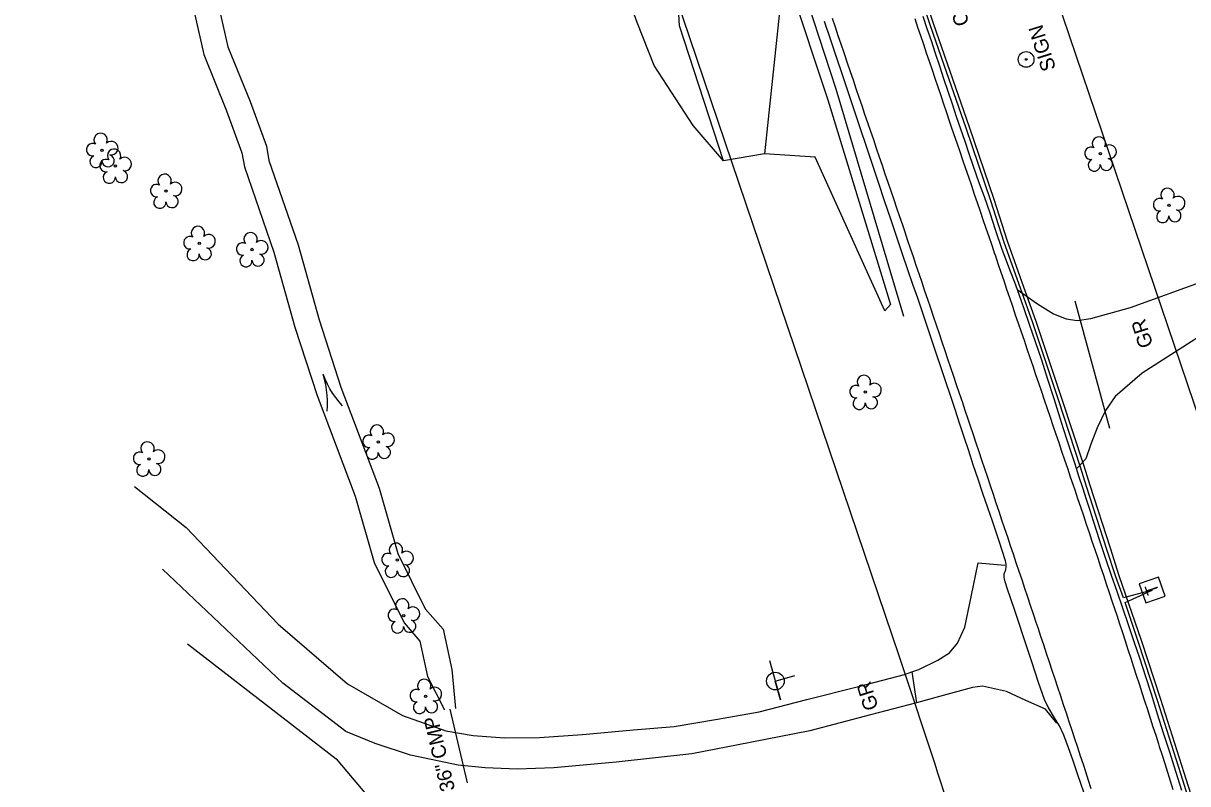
# Model space of a CAD drawing. Extents: x 472260 to 482161, y 489063 to 507124.
# Drawn here: x 481024.5 to 481347.6, y 491870.7 to 492081.8 of the extents above; entities that cross this region are included whole.
import ezdxf

# ---------------------------------------------------------------- set-up
doc = ezdxf.new("R2010")
doc.units = 0
for name, color, linetype in [('Exist Structure Minor Drop Inlet Cogo Elevation', 7, 'Continuous'), ('Exist Structure Minor Pipes CMP 30 Inch', 7, 'Continuous'), ('Prop Drainage Structure Catch Basin Convert From Junction Box Label', 7, 'Continuous'), ('Prop Drainage Structure Drop Inlet Grate 2 Narrow Slots and Sag Grates 840 24 CELL', 7, 'Continuous'), ('Prop Drainage Structure Drop Inlet Grate 2 Wide Slots and Flat Grates 840 20 Label', 7, 'Continuous'), ('Prop Drainage Structure Pipe CSP 30in Label', 7, 'Continuous'), ('Prop Drainage Structure Pipe RCP 15in Class III', 7, 'Continuous'), ('Prop Drainage Structure Pipe RCP 18in Class III', 7, 'Continuous'), ('Prop Drainage Structure Pipe RCP 24in Class III', 7, 'Continuous'), ('Prop Drainage Structure Pipe RCP 48in Class IV', 7, 'Continuous'), ('Prop Drainage Structure Pipe Stub Out CELL', 7, 'Continuous'), ('Prop Drainage Structure Plot Symbol 50 Scale CELL', 7, 'Continuous'), ('Prop Drainage Structure Tops and Inverts LABEL', 7, 'Continuous'), ('Prop Earthen Structure Base Ditch Lateral Detail Label', 7, 'Continuous'), ('Prop Earthen Structure Berm Ditch Detail Label', 7, 'Continuous'), ('Prop Earthen Structure Ditch Flow Line', 7, 'Continuous'), ('Prop Earthen Structure False Sump Label', 7, 'Continuous'), ('Prop Erosion Rip Rap Class B', 7, 'Continuous'), ('Prop Erosion Rip Rap Pad at Outlet Label', 7, 'Continuous'), ('Prop Erosion Rip Rap Single Stone CELL', 7, 'Continuous'), ('Scratch_Level_8', 7, 'Continuous')]:
    doc.layers.add(name, color=color, linetype=linetype)

msp = doc.modelspace()

# ---------------------------------------------------------------- linework, layer by layer
at = {"layer": 'Exist Structure Minor Drop Inlet Cogo Elevation'}
for p, q in [((481362.22, 491938.28), (481119.25, 492655.94)), ((481267.5, 491906.22), (481024.53, 492623.87))]:
    msp.add_line(p, q, dxfattribs=at)
msp.add_arc((478607.84, 491005.76), 2807.95, 16.9803, 18.70399, dxfattribs=at)
at = {"layer": 'Prop Drainage Structure Catch Basin Convert From Junction Box Label'}
for p, q in [((481337.73, 491924.43), (481329.76, 491922.32)), ((481330.28, 491921.01), (481337.73, 491924.43))]:
    msp.add_line(p, q, dxfattribs=at)
for points in [[(481326.13, 491936.08), (481320.49, 491953.49), (481318.83, 491958.9), (481312.67, 491977.61), (481305.58, 491998.99), (481302.12, 492008.58), (481297.61, 492021.26), (481293.89, 492032.85), (481287.08, 492052.94), (481280.98, 492070.5), (481277.07, 492081.69), (481270.89, 492100.12), (481264.89, 492117.85), (481258.42, 492137.44), (481251.79, 492155.9), (481249, 492164.34), (481245.98, 492173.6), (481240.1, 492190.35), (481234.35, 492207.23), (481229.22, 492222.9)], [(481325.18, 491935.77), (481319.53, 491953.19), (481317.88, 491958.6), (481311.72, 491977.3), (481304.64, 491998.67), (481301.18, 492008.24), (481296.66, 492020.94), (481292.94, 492032.53), (481286.13, 492052.62), (481280.03, 492070.17), (481276.12, 492081.37), (481269.94, 492099.8), (481263.94, 492117.54), (481257.47, 492137.11), (481250.85, 492155.58), (481248.05, 492164.03), (481245.04, 492173.28), (481239.15, 492190.03), (481233.4, 492206.91), (481228.95, 492220.49)], [(481329.76, 491922.32), (481327.65, 491928.14), (481325.18, 491935.77)], [(481359.82, 491830.99), (481352.88, 491853.99), (481346.61, 491873.75), (481340.18, 491894.14), (481334.78, 491910.5), (481328.6, 491928.45), (481326.13, 491936.08)], [(481358.87, 491830.7), (481351.92, 491853.69), (481345.65, 491873.45), (481339.23, 491893.84), (481333.84, 491910.18), (481330.28, 491921.01)]]:
    msp.add_lwpolyline(points, dxfattribs=at)
at = {"layer": 'Prop Drainage Structure Drop Inlet Grate 2 Narrow Slots and Sag Grates 840 24 CELL'}
for points in [[(481320.81, 491869.27), (481320.06, 491871.65), (481319.3, 491874.03), (481318.67, 491876.04), (481317.88, 491878.41), (481317.1, 491880.78), (481316.31, 491883.15), (481315.52, 491885.53), (481314.73, 491887.9), (481313.95, 491890.27), (481313.16, 491892.64), (481312.37, 491895.02), (481311.58, 491897.39), (481310.8, 491899.76), (481310.01, 491902.13), (481309.22, 491904.5), (481308.43, 491906.88), (481307.65, 491909.25), (481306.86, 491911.62), (481306.07, 491913.99), (481305.59, 491915.44), (481304.8, 491917.81), (481304.01, 491920.18), (481303.21, 491922.55), (481302.42, 491924.92), (481301.63, 491927.29), (481300.83, 491929.66), (481300.04, 491932.03), (481299.25, 491934.4), (481298.45, 491936.77), (481297.66, 491939.14), (481296.87, 491941.51), (481296.07, 491943.88), (481295.28, 491946.25), (481294.49, 491948.62), (481293.7, 491951), (481292.9, 491953.37), (481292.11, 491955.74), (481291.32, 491958.11), (481290.52, 491960.48), (481289.73, 491962.85), (481288.94, 491965.22), (481288.14, 491967.59), (481287.35, 491969.96), (481286.69, 491971.94), (481285.89, 491974.31), (481285.09, 491976.68), (481284.29, 491979.05), (481283.49, 491981.42), (481282.69, 491983.78), (481281.89, 491986.15), (481281.09, 491988.52), (481280.29, 491990.89), (481279.49, 491993.26), (481278.69, 491995.63), (481277.89, 491997.99), (481277.09, 492000.36), (481276.29, 492002.73), (481275.49, 492005.1), (481274.69, 492007.47), (481273.89, 492009.84), (481273.09, 492012.2), (481272.29, 492014.57), (481271.49, 492016.94), (481270.69, 492019.31), (481269.89, 492021.68), (481269.09, 492024.05), (481268.53, 492025.72), (481267.72, 492028.09), (481266.92, 492030.45), (481266.11, 492032.82), (481265.31, 492035.19), (481264.5, 492037.55), (481263.7, 492039.92), (481262.89, 492042.29), (481262.09, 492044.65), (481261.28, 492047.02), (481260.48, 492049.39), (481259.67, 492051.75), (481258.87, 492054.12), (481258.06, 492056.49), (481257.26, 492058.85), (481256.45, 492061.22), (481255.65, 492063.59), (481254.84, 492065.95), (481254.04, 492068.32), (481253.23, 492070.69), (481252.43, 492073.05), (481252.24, 492073.59), (481251.45, 492075.95), (481250.65, 492078.32), (481249.85, 492080.69), (481249.05, 492083.06)], [(481271.85, 492083.08), (481272.65, 492080.71), (481273.46, 492078.34), (481274.26, 492075.97), (481275.06, 492073.6), (481275.86, 492071.24), (481276.66, 492068.87), (481277.46, 492066.5), (481278.26, 492064.13), (481279.06, 492061.76), (481279.86, 492059.4), (481280.66, 492057.03), (481281.46, 492054.66), (481281.92, 492053.31), (481282.73, 492050.95), (481283.53, 492048.58), (481284.34, 492046.22), (481285.15, 492043.85), (481285.95, 492041.49), (481286.76, 492039.12), (481287.57, 492036.75), (481288.37, 492034.39), (481289.18, 492032.02), (481289.99, 492029.66), (481290.8, 492027.29), (481291.6, 492024.92), (481292.41, 492022.56), (481293.22, 492020.19), (481294.02, 492017.83), (481294.15, 492017.47), (481294.95, 492015.1), (481295.75, 492012.73), (481296.56, 492010.37), (481297.36, 492008), (481298.16, 492005.63), (481298.97, 492003.26), (481299.77, 492000.9), (481300.57, 491998.53), (481301.38, 491996.16), (481302.18, 491993.8), (481302.98, 491991.43), (481303.78, 491989.06), (481304.59, 491986.7), (481305.39, 491984.33), (481306.19, 491981.96), (481307, 491979.59), (481307.8, 491977.23), (481308.6, 491974.86), (481309.41, 491972.49), (481310.21, 491970.13), (481311.01, 491967.76), (481311.82, 491965.39), (481312.62, 491963.03), (481313.42, 491960.66), (481314.23, 491958.29), (481315.03, 491955.93), (481315.83, 491953.56), (481316.27, 491952.28), (481317.06, 491949.91), (481317.86, 491947.54), (481318.65, 491945.17), (481319.44, 491942.8), (481320.24, 491940.43), (481321.03, 491938.06), (481321.83, 491935.69), (481322.62, 491933.32), (481323.42, 491930.95), (481324.21, 491928.58), (481325, 491926.21), (481325.8, 491923.84), (481326.59, 491921.47), (481327.39, 491919.1), (481327.93, 491917.47), (481328.7, 491915.09), (481329.47, 491912.71), (481330.24, 491910.34), (481331.01, 491907.96), (481331.78, 491905.58), (481332.55, 491903.2), (481333.32, 491900.83), (481334.09, 491898.45), (481334.86, 491896.07), (481335.63, 491893.69), (481336.4, 491891.32), (481337.17, 491888.94), (481337.94, 491886.56), (481338.71, 491884.18), (481339.48, 491881.8), (481339.72, 491881.06), (481340.48, 491878.68), (481341.23, 491876.3), (481341.99, 491873.91), (481342.74, 491871.53), (481343.49, 491869.15)]]:
    msp.add_lwpolyline(points, dxfattribs=at)
at = {"layer": 'Prop Drainage Structure Drop Inlet Grate 2 Wide Slots and Flat Grates 840 20 Label'}
for p, q in [((481046.38, 492046.52), (481046.38, 492046.52)), ((481323.37, 492045.55), (481323.37, 492045.55)), ((481050.09, 492042.14), (481050.09, 492042.14)), ((481064.12, 492035.2), (481064.12, 492035.2)), ((481342.38, 492031.25), (481342.38, 492031.25)), ((481073.36, 492020.69), (481073.36, 492020.69)), ((481087.99, 492018.99), (481087.99, 492018.99)), ((481258.14, 491979.4), (481258.14, 491979.4)), ((481123.05, 491965.58), (481123.05, 491965.58)), ((481059.39, 491960.89), (481059.39, 491960.89)), ((481128.31, 491932.79), (481128.31, 491932.79)), ((481130.07, 491917.34), (481130.07, 491917.34)), ((481136.15, 491895.01), (481136.15, 491895.01))]:
    msp.add_line(p, q, dxfattribs=at)
for centre in [(481046.38, 492046.52), (481323.37, 492045.55), (481050.09, 492042.14), (481064.12, 492035.2), (481342.38, 492031.25), (481073.36, 492020.69), (481087.99, 492018.99), (481258.14, 491979.4), (481123.05, 491965.58), (481059.39, 491960.89), (481128.31, 491932.79), (481130.07, 491917.34), (481136.15, 491895.01)]:
    msp.add_circle(centre, 0.326, dxfattribs=at)
for centre, radius, start, end in [((481046, 492049.4), 1.86, 330.1651, 219.7134), ((481043.78, 492046.68), 1.73, 62.6636, 279.3457), ((481048.93, 492047.11), 1.9, 257.1011, 134.1999), ((481320.76, 492045.7), 1.73, 62.6636, 279.3457), ((481322.98, 492048.42), 1.86, 330.1651, 219.7134), ((481325.91, 492046.14), 1.9, 257.1011, 134.1999), ((481044.68, 492043.4), 1.69, 111.5671, 6.231), ((481047.49, 492042.3), 1.73, 62.6636, 279.3457), ((481048.06, 492043.63), 1.7, 181.2822, 74.56), ((481049.71, 492045.02), 1.86, 330.1651, 219.7134), ((481052.64, 492042.73), 1.9, 257.1011, 134.1999), ((481321.66, 492042.43), 1.69, 111.5671, 6.231), ((481325.04, 492042.65), 1.7, 181.2822, 74.56), ((481051.76, 492039.24), 1.7, 181.2822, 74.56), ((481048.39, 492039.02), 1.69, 111.5671, 6.231), ((481063.73, 492038.07), 1.86, 330.1651, 219.7134), ((481066.66, 492035.79), 1.9, 257.1011, 134.1999), ((481061.51, 492035.35), 1.73, 62.6636, 279.3457), ((481341.99, 492034.12), 1.86, 330.1651, 219.7134), ((481062.41, 492032.08), 1.69, 111.5671, 6.231), ((481065.79, 492032.3), 1.7, 181.2822, 74.56), ((481339.77, 492031.4), 1.73, 62.6636, 279.3457), ((481344.93, 492031.83), 1.9, 257.1011, 134.1999), ((481340.67, 492028.12), 1.69, 111.5671, 6.231), ((481344.05, 492028.35), 1.7, 181.2822, 74.56), ((481072.97, 492023.57), 1.86, 330.1651, 219.7134), ((481070.75, 492020.85), 1.73, 62.6636, 279.3457), ((481075.91, 492021.28), 1.9, 257.1011, 134.1999), ((481087.61, 492021.86), 1.86, 330.1651, 219.7134), ((481090.54, 492019.58), 1.9, 257.1011, 134.1999), ((481071.65, 492017.57), 1.69, 111.5671, 6.231), ((481075.03, 492017.8), 1.7, 181.2822, 74.56), ((481085.39, 492019.14), 1.73, 62.6636, 279.3457), ((481086.29, 492015.87), 1.69, 111.5671, 6.231), ((481089.66, 492016.09), 1.7, 181.2822, 74.56), ((481257.76, 491982.27), 1.86, 330.1651, 219.7134), ((481255.54, 491979.55), 1.73, 62.6636, 279.3457), ((481260.69, 491979.99), 1.9, 257.1011, 134.1999), ((481256.44, 491976.28), 1.69, 111.5671, 6.231), ((481259.82, 491976.5), 1.7, 181.2822, 74.56), ((481122.66, 491968.45), 1.86, 330.1651, 219.7134), ((481120.44, 491965.73), 1.73, 62.6636, 279.3457), ((481125.6, 491966.16), 1.9, 257.1011, 134.1999), ((481059, 491963.77), 1.86, 330.1651, 219.7134), ((481061.94, 491961.48), 1.9, 257.1011, 134.1999), ((481121.34, 491962.46), 1.69, 111.5671, 6.231), ((481124.72, 491962.68), 1.7, 181.2822, 74.56), ((481056.78, 491961.05), 1.73, 62.6636, 279.3457), ((481057.68, 491957.77), 1.69, 111.5671, 6.231), ((481061.06, 491957.99), 1.7, 181.2822, 74.56), ((481127.92, 491935.67), 1.86, 330.1651, 219.7134), ((481125.7, 491932.95), 1.73, 62.6636, 279.3457), ((481130.86, 491933.38), 1.9, 257.1011, 134.1999), ((481126.6, 491929.67), 1.69, 111.5671, 6.231), ((481129.98, 491929.89), 1.7, 181.2822, 74.56), ((481129.69, 491920.21), 1.86, 330.1651, 219.7134), ((481127.47, 491917.49), 1.73, 62.6636, 279.3457), ((481132.62, 491917.93), 1.9, 257.1011, 134.1999), ((481128.37, 491914.22), 1.69, 111.5671, 6.231), ((481131.75, 491914.44), 1.7, 181.2822, 74.56), ((481135.77, 491897.88), 1.86, 330.1651, 219.7134), ((481133.55, 491895.17), 1.73, 62.6636, 279.3457), ((481138.7, 491895.6), 1.9, 257.1011, 134.1999), ((481134.45, 491891.89), 1.69, 111.5671, 6.231), ((481137.82, 491892.11), 1.7, 181.2822, 74.56)]:
    msp.add_arc(centre, radius, start, end, dxfattribs=at)
at = {"layer": 'Prop Drainage Structure Pipe CSP 30in Label'}
msp.add_line((481147.8, 491870.99), (481142.97, 491891.41), dxfattribs=at)
at = {"layer": 'Prop Drainage Structure Pipe RCP 15in Class III'}
for radius in [2.18, 0.24]:
    msp.add_circle((481302.77, 492071.73), radius, dxfattribs=at)
at = {"layer": 'Prop Drainage Structure Pipe RCP 18in Class III'}
for points in [[(481300.24, 492007.9), (481305.9, 492003.94), (481310.36, 492001.12), (481313.85, 491999.71), (481316.93, 491999.27), (481320.69, 491999.85), (481331.71, 492002.86), (481352.2, 492010.34), (481369.68, 492018.69), (481388.23, 492026.73), (481407.41, 492036.64), (481418.39, 492042.31), (481422.78, 492046.64), (481423.47, 492050.45), (481422.46, 492053.66), (481412.42, 492071.99)], [(481350.89, 491994.81), (481334.92, 491984.69), (481327.44, 491978.21), (481324.81, 491974.3), (481322.48, 491969.54), (481320.76, 491964.95), (481319.34, 491960.85), (481316.92, 491958.3)], [(481055.41, 491953.22), (481069.68, 491941.82), (481095.21, 491914.98), (481114.49, 491898.41)], [(481113.99, 491885.26), (481096.55, 491898.62), (481063.11, 491930.31)], [(481114.49, 491898.41), (481129.75, 491889.68), (481141.74, 491885.42), (481149.33, 491884.15), (481158.02, 491883.49), (481167.72, 491883.59), (481179.65, 491884.38), (481193.81, 491885.73), (481205.15, 491886.6), (481217.18, 491888.65), (481228.69, 491890.71), (481241.95, 491894.14), (481256.6, 491897.81), (481269.02, 491901.08), (481271.02, 491901.75)], [(481272.39, 491893.22), (481259.56, 491889.85), (481242.71, 491885.38), (481226.21, 491882.16), (481210.03, 491879.07), (481189.01, 491876.7), (481171.77, 491875.12), (481161.51, 491874.78), (481152.72, 491875.12), (481145.16, 491875.86), (481131.93, 491878.61), (481122.16, 491881.88), (481113.99, 491885.26)]]:
    msp.add_lwpolyline(points, dxfattribs=at)
at = {"layer": 'Prop Drainage Structure Pipe RCP 24in Class III'}
for points in [[(481064.46, 492148.19), (481070.83, 492122.6), (481075.39, 492107.7), (481078.53, 492087.42), (481081.3, 492075.22), (481087.45, 492060.02), (481091.97, 492047.67), (481092.67, 492043.72), (481100.76, 492020.33), (481106.61, 491999.47), (481112.65, 491980.78), (481123.24, 491952.71), (481128.44, 491934.66), (481136.06, 491919.26), (481141.04, 491913.58), (481143.46, 491902.4), (481144.41, 491891.56)], [(481057.67, 492146.5), (481064.08, 492120.73), (481068.55, 492106.14), (481071.65, 492086.11), (481074.6, 492073.12), (481080.91, 492057.5), (481085.18, 492045.84), (481085.88, 492041.95), (481094.07, 492018.24), (481099.91, 491997.45), (481106.04, 491978.47), (481116.59, 491950.5), (481121.89, 491932.11), (481130.19, 491915.34), (481134.58, 491910.33), (481136.71, 491900.48), (481141.35, 491891.23)]]:
    msp.add_lwpolyline(points, dxfattribs=at)
at = {"layer": 'Prop Drainage Structure Pipe Stub Out CELL'}
for points in [[(481274.1, 492083.71), (481275.23, 492080.36), (481276.38, 492076.95), (481277.54, 492073.47), (481278.71, 492069.95), (481279.88, 492066.44), (481281.06, 492062.93), (481282.23, 492059.42), (481283.4, 492055.93), (481284.56, 492052.47), (481285.72, 492049.03), (481286.87, 492045.63), (481287.96, 492042.44), (481289.77, 492037.29), (481291.11, 492033.69), (481292.68, 492029.21), (481294.19, 492024.58), (481296.04, 492019.09), (481298.02, 492013.74), (481299.79, 492009.19), (481300.85, 492006.29), (481302.15, 492002.59), (481303.64, 491998.29), (481305.3, 491993.45), (481307, 491988.34), (481308.72, 491983.02), (481310.42, 491977.68), (481312.13, 491972.24), (481313.07, 491969.29), (481314.07, 491966.16), (481315.15, 491962.84), (481316.25, 491959.47), (481317.33, 491956.15), (481318.38, 491952.9), (481319.41, 491949.72), (481320.41, 491946.63), (481321.37, 491943.68), (481323.17, 491938.2), (481324.83, 491933.21), (481326.38, 491928.63), (481327.9, 491924.18), (481329.46, 491919.58), (481331.05, 491914.89), (481332.66, 491910.18), (481334.28, 491905.38), (481335.89, 491900.45), (481337.52, 491895.38), (481339.16, 491890.17), (481340.83, 491884.88), (481342.52, 491879.56), (481344.21, 491874.24), (481345.87, 491868.93)], [(481318.76, 491868.39), (481317.14, 491873.17), (481315.7, 491877.36), (481314.55, 491880.67), (481313.24, 491884.23), (481312.04, 491886.81), (481310.67, 491889.06), (481308.84, 491891.95), (481307.83, 491894.13), (481306.18, 491898.83), (481304.35, 491904.53), (481303.26, 491907.88), (481302.06, 491911.52), (481300.75, 491915.45), (481299.53, 491919.08), (481297.61, 491924.77), (481296.94, 491926.8), (481296.73, 491927.62), (481296.68, 491928), (481296.66, 491928.37), (481296.67, 491928.71), (481296.71, 491929), (481296.78, 491929.26), (481296.98, 491929.66), (481297.06, 491929.86), (481297.12, 491930.08), (481297.16, 491930.3), (481297.2, 491930.84), (481297.19, 491931.53), (481297.11, 491932.25), (481297.04, 491932.57), (481295.32, 491938.07), (481293.47, 491943.55), (481292.18, 491947.27), (481290.79, 491951.3), (481289.43, 491955.28), (481288.11, 491959.2), (481286.83, 491963.07), (481285.57, 491966.91), (481284.31, 491970.75), (481283.04, 491974.6), (481281.77, 491978.44), (481280.5, 491982.28), (481279.22, 491986.13), (481277.93, 491989.98), (481276.64, 491993.83), (481275.34, 491997.69), (481274.02, 492001.56), (481272.7, 492005.44), (481271.37, 492009.32), (481269.98, 492013.37), (481268.5, 492017.73), (481266.91, 492022.39), (481265.22, 492027.37), (481263.5, 492032.48), (481261.8, 492037.55), (481260.12, 492042.57), (481258.46, 492047.56), (481256.81, 492052.52), (481255.15, 492057.49), (481253.49, 492062.46), (481251.82, 492067.43), (481250.15, 492072.4), (481248.5, 492077.36), (481246.85, 492082.31)]]:
    msp.add_lwpolyline(points, dxfattribs=at)
at = {"layer": 'Prop Drainage Structure Plot Symbol 50 Scale CELL'}
msp.add_lwpolyline([(481268.81, 492000.43), (481250.05, 492063.45), (481229.61, 492126.12), (481209.51, 492187.09), (481191.12, 492240.55), (481159.92, 492332.85)], dxfattribs=at)
at = {"layer": 'Prop Drainage Structure Tops and Inverts LABEL'}
for points in [[(481218.82, 492043.64), (481210.36, 492053.43), (481199.59, 492070.01), (481194.83, 492082.01), (481182.3, 492117.17), (481166.69, 492152.71), (481152.18, 492170.83), (481143.63, 492202.94), (481118.35, 492248.52), (481084.64, 492335.71)], [(481155.16, 492335.93), (481180.47, 492261.79), (481204.48, 492191.93), (481226.94, 492123.21), (481247.75, 492060.54), (481265.18, 492003.69), (481263.56, 492001.99), (481244.2, 492044.6), (481230.17, 492045.55)]]:
    msp.add_lwpolyline(points, dxfattribs=at)
at = {"layer": 'Prop Earthen Structure Base Ditch Lateral Detail Label'}
msp.add_line((481233.19, 491899.23), (481233.19, 491899.23), dxfattribs=at)
msp.add_lwpolyline([(481231.6, 491904.95), (481234.6, 491894.02), (481233.17, 491899.23), (481238.61, 491900.74)], dxfattribs=at)
msp.add_circle((481233.2, 491899.23), 2.45, dxfattribs=at)
at = {"layer": 'Prop Earthen Structure Ditch Flow Line'}
msp.add_line((481271.02, 491901.75), (481272.39, 491893.22), dxfattribs=at)
for points in [[(481271.02, 491901.75), (481273.02, 491902.41), (481278.31, 491905.04), (481281.52, 491907.06), (481283.77, 491909.77), (481285.75, 491914.22), (481287.04, 491920.33), (481288.18, 491925.78), (481289.47, 491931.99), (481296.84, 491931.41)], [(481311.24, 491887.5), (481308.1, 491891.44), (481302.65, 491893.83), (481297.33, 491896.28), (481290.63, 491897.83), (481287.92, 491897.48), (481278.77, 491894.96), (481272.39, 491893.22)]]:
    msp.add_lwpolyline(points, dxfattribs=at)
at = {"layer": 'Prop Erosion Rip Rap Class B'}
msp.add_line((481337.73, 491924.43), (481337.73, 491924.43), dxfattribs=at)
msp.add_lwpolyline([(481341.3, 491922.79), (481339.45, 491928.07), (481334.17, 491926.22), (481336.02, 491920.94), (481341.3, 491922.79)], dxfattribs=at)
at = {"layer": 'Prop Erosion Rip Rap Pad at Outlet Label'}
for points in [[(481219.66, 492113.73), (481234.28, 492084), (481230.17, 492045.55), (481218.82, 492043.64), (481206.62, 492081.07), (481205.06, 492109.1), (481219.66, 492113.73)], [(481070.09, 491909.52), (481111.3, 491877.6), (481138.11, 491845.92), (481161.25, 491844.15), (481174.3, 491827.64)]]:
    msp.add_lwpolyline(points, dxfattribs=at)
at = {"layer": 'Prop Erosion Rip Rap Single Stone CELL'}
msp.add_line((481326.02, 491969.33), (481316.36, 492004.64), dxfattribs=at)
at = {"layer": 'Scratch_Level_8'}
msp.add_line((481109.34, 491979.63), (481109.34, 491979.63), dxfattribs=at)
for points in [[(481113.13, 491975.64), (481112.13, 491976.71), (481111.23, 491977.91), (481110.36, 491979.1), (481109.6, 491980.34), (481108.9, 491981.64), (481108.26, 491983), (481107.72, 491984.36)], [(481108.8, 491974.15), (481108.94, 491975.61), (481108.91, 491977.11), (481108.87, 491978.59), (481108.7, 491980.03), (481108.45, 491981.49), (481108.12, 491982.95), (481107.72, 491984.36)]]:
    msp.add_lwpolyline(points, dxfattribs=at)

# ---------------------------------------------------------------- texts
at = {"layer": 'Exist Structure Minor Pipes CMP 30 Inch'}
msp.add_text('CONC HW', height=4, rotation=108.9605, dxfattribs=at).set_placement((481287.1, 492081.78))
at = {"layer": 'Prop Drainage Structure Pipe RCP 48in Class IV'}
msp.add_text('SIGN', height=4, rotation=107.5164, dxfattribs=at).set_placement((481311.08, 492069.22))
at = {"layer": 'Prop Earthen Structure Berm Ditch Detail Label'}
msp.add_text('36" CMP', height=4, rotation=103.3262, dxfattribs=at).set_placement((481144.34, 491869.11))
at = {"layer": 'Prop Earthen Structure False Sump Label'}
for p in [(481338.06, 491992.41), (481261.85, 491891.81)]:
    msp.add_text('GR', height=4, rotation=107.5164, dxfattribs=at).set_placement(p)
at = {"layer": 'Prop Erosion Rip Rap Class B'}
msp.add_text('T', height=3.42, rotation=109.3364, dxfattribs=at).set_placement((481339.73, 491923.93))

doc.saveas('drawing.dxf')
